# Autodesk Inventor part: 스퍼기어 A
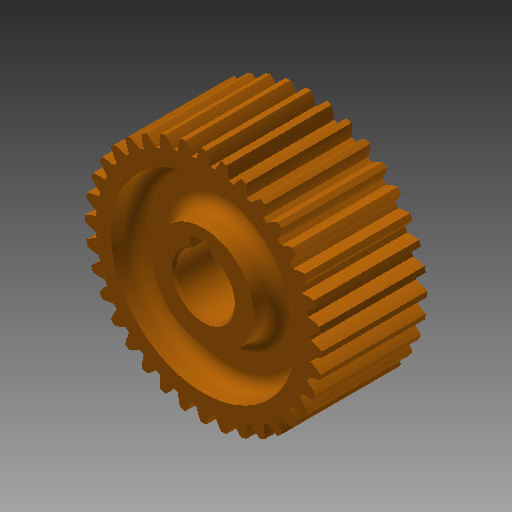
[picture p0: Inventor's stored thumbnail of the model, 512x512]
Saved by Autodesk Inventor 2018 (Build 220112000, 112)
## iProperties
Created: 2020-04
Part Number: 스퍼기어 A
Material: 강철, 연강
Document SubType Name: Modeling
Designer: mduedu
Categories: <?xml version="1.0" encoding="UTF-16"?> <MemberInstance><Categories><FamilyTemplate><FamilyTemplateParameter ValueType="xs:double" Id="1" ObjectReferenceKey="da
Density: 7.86 g/cm^3
Mass: 321.469 g
Surface Area: 147.737 cm^2
Volume: 40.8993 cm^3
Appearance: 주황색
Author: mduedu
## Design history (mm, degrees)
sketch "Sketch1"
  geometry: C1 r 28.2 at (0, 0)
  constraints: 1 centre point
  dimensions: "d0" = 56.4 diameter of C1 (= da_da)
extrude "Extrusion1" new body sketch "Sketch1" distance "d1" = 25 (= da_b); taper "d2" = 0 deg
workplane "Work Plane2"
sketch "Sketch2"
  geometry: C1 r 28.2 at (0, 0) reference; C2 r 27 at (0, 0)
  constraints: 1 centre point, 1 coincident
  dimensions: "d3" = 54 diameter of C2 (= da_dw)
feature "피치 지름" sketch "Sketch2" dims "d4" = 10, "d5" = 0
workplane "Work Plane8"
workplane "Work Plane9"
feature "스퍼 기어" dims "da_b" = 25, "da_d" = 54, "da_aw" = 45, "da_da" = 56.4, "da_df" = 51.129, "da_dw" = 54, angle "da_beta" = 0 deg, "da_lefttooth" = 0, "da_righttooth" = 0
node "작업 평면11"
sketch "스케치3"
  geometry: C1 r 12 at (0, 0); C2 r 22 at (0, 0); 1 further point
  constraints: 2 centre point, 2 coincident
  dimensions: "d49" = 24 diameter of C1; "d50" = 44 diameter of C2
extrude "돌출2" cut sketch "스케치3" distance "d51" = 6; taper "d52" = 0 deg
fillet "모깎기1" dims "d53" = 3
sketch "스케치4" dims "d17" = 0
  geometry: L1 (-3.06, 6.296)-(1.921, 6.731); L2 (1.921, 6.731)-(1.68, 9.483); L3 (1.68, 9.483)-(-3.301, 9.047); L4 (-3.301, 9.047)-(-3.06, 6.296); L5 (-3.728, 42.608)-(3.728, -42.608) reference; A1 r 7 centre (0, 0) between (-3.06, 6.296) and (1.921, 6.731); 1 further point
  constraints: 8 end point, 4 perpendicular, 2 point on circle, 1 centre point, 1 coincident
  dimensions: "d54" = 14 diameter of A1; "d63" = 16.3 dimension on A1 L3; "d64" = 5 distance of L2.end L3.end
extrude "돌출3" cut sketch "스케치4" extent not by distance; stored distance "d58" = 6; taper "d59" = 0 deg
chamfer "모따기1" distance "d60" = 0.5; stored, may be unused: second distance "d61" = 2, angle "d62" = 45 deg
body "Solid1"
mirror "대칭1"
body "Srf1"
other parameters: "d16" = 45 (= da_aw), "d34" = 5 deg (computed from da_z), "d39" = 0, "d41" = 0, "d43" = 45 (= da_aw), "d46" = 45 (= da_aw), "d47" = 0, "d48" = 0
